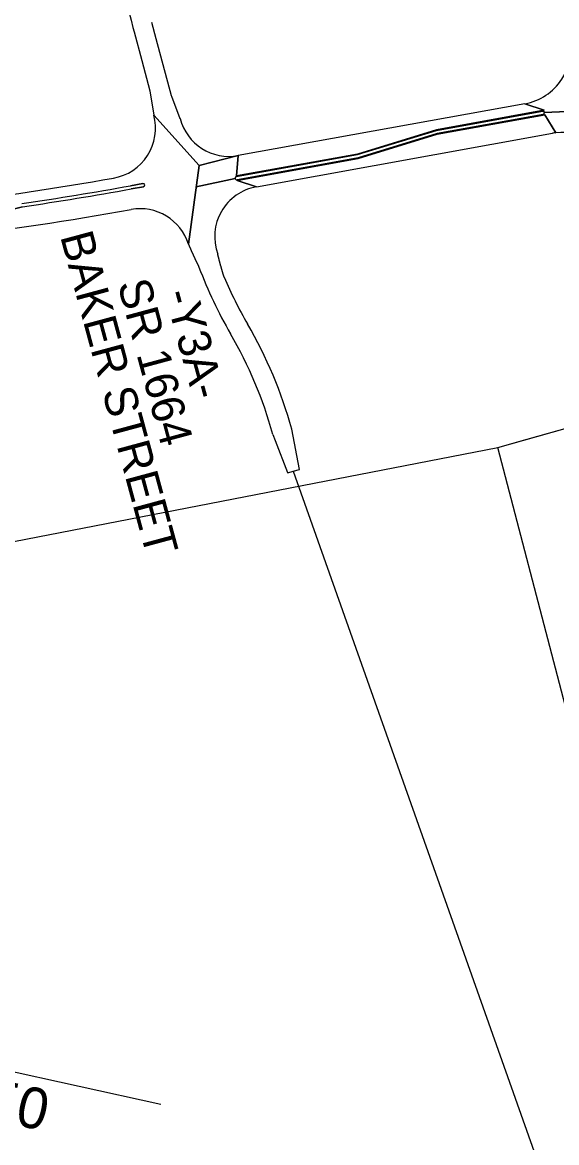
# Model space of a CAD drawing. Extents: x 1609449 to 1623942, y 894240 to 902860.
# Drawn here: x 1620757 to 1621409, y 896944 to 898313 of the extents above; entities that cross this region are included whole.
import ezdxf

# ---------------------------------------------------------------- set-up
doc = ezdxf.new("R2010")
doc.units = 0
for name, color, linetype in [('Old_Level_1', 7, 'Continuous'), ('Prop Horizontal Alignment Station Label', 7, 'Continuous'), ('Prop Roadway Bridge', 7, 'Continuous'), ('Prop Shade Light', 7, 'Continuous'), ('Prop Shade Medium', 7, 'Continuous')]:
    doc.layers.add(name, color=color, linetype=linetype)

msp = doc.modelspace()

# ---------------------------------------------------------------- linework, layer by layer
at = {"layer": 'Old_Level_1'}
for points in [[(1620396.2, 898448.3), (1620661.8, 898448.3), (1620661.8, 897662.4), (1621336.9, 897793.5), (1621466.5, 897830.2), (1621864, 897934.4), (1622007.2, 897969.4), (1621831.8, 898938.5), (1620355.8, 898671.4)], [(1621336.9, 897793.5), (1621372.5, 897803.4), (1621466.5, 897830.2), (1621756.4, 897907.9), (1621864, 897934.4), (1622015.4, 897355), (1621487.4, 897217.1)]]:
    msp.add_lwpolyline(points, close=True, dxfattribs=at)
at = {"layer": 'Prop Horizontal Alignment Station Label'}
msp.add_line((1621087, 897764.3), (1621535, 896499.9), dxfattribs=at)
at = {"layer": 'Prop Roadway Bridge'}
msp.add_line((1620274, 897134.9), (1620925.3, 896991.4), dxfattribs=at)
at = {"layer": 'Prop Shade Light'}
for p, q in [((1620912, 898229), (1620916.8, 898199.3)), ((1621370, 898213.2), (1621019.9, 898149.8)), ((1621393.4, 898205.2), (1621370, 898213.2)), ((1621393.4, 898205.2), (1621370, 898213.2)), ((1621370, 898213.2), (1621393.4, 898205.2)), ((1620916.8, 898199.3), (1620972.2, 898137.9)), ((1620972.2, 898137.9), (1620916.8, 898199.3)), ((1620916.8, 898199.3), (1620972.2, 898137.9)), ((1621261.8, 898181.4), (1621393.4, 898205.2)), ((1621393.4, 898205.2), (1621261.8, 898181.4)), ((1621262, 898180.7), (1621391.6, 898204.1)), ((1621392.3, 898200.2), (1621262.7, 898176.8)), ((1621394.4, 898199.8), (1621262.8, 898176)), ((1621262.8, 898176), (1621394.4, 898199.8)), ((1621393.9, 898202.3), (1621497.1, 898207.8)), ((1621497.1, 898207.8), (1621393.9, 898202.3)), ((1621393.9, 898202.3), (1621497.1, 898207.8)), ((1621408, 898177.1), (1621394.4, 898199.8)), ((1621407.6, 898177.7), (1621394.4, 898199.8)), ((1621394.4, 898199.8), (1621407.6, 898177.7)), ((1621042.2, 898111.7), (1621403.4, 898177.1)), ((1621165.4, 898151.8), (1621261.8, 898181.4)), ((1621261.8, 898181.4), (1621165.4, 898151.8)), ((1621165.5, 898151), (1621262, 898180.7)), ((1621262.7, 898176.8), (1621166.2, 898147.1)), ((1621262.8, 898176), (1621166.3, 898146.4)), ((1621166.3, 898146.4), (1621262.8, 898176)), ((1620972.2, 898137.9), (1621019.9, 898149.8)), ((1620972.2, 898137.9), (1621019.9, 898149.8)), ((1621019.9, 898149.8), (1620972.2, 898137.9)), ((1621017.8, 898125.1), (1621165.4, 898151.8)), ((1621165.4, 898151.8), (1621017.8, 898125.1)), ((1621017.8, 898125.1), (1621019.9, 898149.8)), ((1621019.9, 898149.8), (1621017.8, 898125.1)), ((1621017.8, 898125.1), (1621019.9, 898149.8)), ((1621017.9, 898124.3), (1621165.5, 898151)), ((1621166.2, 898147.1), (1621018.6, 898120.4)), ((1621166.3, 898146.4), (1621018.7, 898119.6)), ((1621018.7, 898119.6), (1621166.3, 898146.4)), ((1620972.2, 898137.9), (1620959.2, 898041.5)), ((1620959.2, 898041.5), (1620972.2, 898137.9)), ((1620972.2, 898137.9), (1620968.7, 898111.9)), ((1620888.4, 898113.1), (1620903.7, 898115.8)), ((1621016.3, 898122), (1620968.7, 898111.9)), ((1621016.3, 898122), (1620968.7, 898111.9)), ((1620968.7, 898111.9), (1621016.3, 898122)), ((1621018.7, 898119.6), (1621042.2, 898111.7)), ((1621018.7, 898119.6), (1621042.2, 898111.7)), ((1621042.2, 898111.7), (1621018.7, 898119.6)), ((1620904.4, 898111.9), (1620889.1, 898109.1)), ((1620968.7, 898111.9), (1620959.2, 898041.5)), ((1621094.9, 897766.4), (1621085.3, 897815.6))]:
    msp.add_line(p, q, dxfattribs=at)
for points in [[(1620891.5, 898306.4), (1620892.9, 898300.9), (1620902.1, 898266.1), (1620912, 898229)], [(1620938.5, 898222.9), (1620919.9, 898292.6), (1620914.7, 898312.5)], [(1620949, 898194.9), (1620938.8, 898221.9), (1620938.5, 898222.9)], [(1621062.2, 897809.3), (1621065, 897802.1), (1621065, 897802.1), (1621080.3, 897762.7), (1621080.4, 897762.4)], [(1621080.4, 897762.4), (1621087, 897764.3), (1621094.9, 897766.4)]]:
    msp.add_lwpolyline(points, dxfattribs=at)
for centre, radius, start, end in [((1621418.2, 898446.2), 545, 179.3265, 194.8727), ((1621357.9, 898280.1), 68, 280.2581, 13.8394), ((1620856.9, 898183.4), 62, 279.9888, 14.8727), ((1621391.9, 898202.2), 2, 4.5811, 100.2599), ((1621391.9, 898202.2), 2, 280.2599, 284.1231), ((1621391.9, 898202.2), 2, 284.1231, 4.5811), ((1621008.9, 898210.9), 62, 194.8727, 280.2581), ((1621415.6, 898110.2), 68, 96.6994, 100.2599), ((1621415.6, 898110.2), 68, 14.985, 96.6994), ((1620177.4, 902041.2), 3979.2, 276.992, 279.9888), ((1620904, 898113.9), 2, 280.2599, 100.2599), ((1621018.3, 898122.3), 2, 100.2599, 188.9181), ((1621018.3, 898122.3), 2, 188.9181, 280.2599), ((1620177.4, 902041.2), 3992, 278.333, 280.2599), ((1620177.4, 902041.2), 3996, 278.333, 280.2599), ((1621053.2, 898050.7), 62, 100.2599, 199.8507), ((1620177.4, 902041.2), 4020.7, 276.9195, 280.1956), ((1620900.1, 898023), 62, 17.4099, 100.1956), ((1621482.1, 898205.5), 545, 200.6397, 210.1014), ((1621482.1, 898205.5), 521, 203.0756, 210.1014), ((1620559.9, 897670.9), 545, 15.403, 30.1014), ((1620559.9, 897670.9), 521, 15.403, 30.1014)]:
    msp.add_arc(centre, radius, start, end, dxfattribs=at)
for points in [[(1620959.2, 898041.5), (1620959.4, 898041.1), (1620959.6, 898040.7), (1620959.7, 898040.4), (1620959.9, 898040), (1620960.1, 898039.6), (1620960.2, 898039.2), (1620960.4, 898038.8), (1620960.6, 898038.4), (1620960.7, 898038), (1620960.9, 898037.7), (1620961.1, 898037.3), (1620961.2, 898036.9), (1620961.4, 898036.5), (1620961.6, 898036.1), (1620961.7, 898035.7), (1620961.9, 898035.4), (1620962.1, 898035), (1620962.2, 898034.6), (1620962.4, 898034.2), (1620962.6, 898033.8), (1620962.7, 898033.4), (1620962.9, 898033.1), (1620963.1, 898032.7), (1620963.3, 898032.3), (1620963.4, 898032.1)], [(1620963.4, 898032.1), (1620963.4, 898031.9), (1620963.6, 898031.5), (1620963.8, 898031.2), (1620963.9, 898030.8), (1620964.1, 898030.4), (1620964.3, 898030), (1620964.5, 898029.6), (1620964.6, 898029.3), (1620964.8, 898028.9), (1620965, 898028.5), (1620965.1, 898028.1), (1620965.3, 898027.7), (1620965.5, 898027.4), (1620965.7, 898027), (1620965.8, 898026.6), (1620966, 898026.2), (1620966.2, 898025.8), (1620966.4, 898025.5), (1620966.5, 898025.1), (1620966.7, 898024.7), (1620966.9, 898024.3), (1620967.1, 898023.9), (1620967.2, 898023.6), (1620967.4, 898023.2), (1620967.6, 898022.8), (1620967.6, 898022.7)], [(1620967.6, 898022.7), (1620967.8, 898022.4), (1620967.9, 898022.1), (1620968.1, 898021.7), (1620968.3, 898021.3), (1620968.5, 898020.9), (1620968.7, 898020.5), (1620968.8, 898020.2), (1620969, 898019.8), (1620969.2, 898019.4), (1620969.4, 898019), (1620969.6, 898018.7), (1620969.7, 898018.3), (1620969.9, 898017.9), (1620970.1, 898017.5), (1620970.3, 898017.2), (1620970.5, 898016.8), (1620970.6, 898016.4), (1620970.8, 898016), (1620971, 898015.7), (1620971.2, 898015.3), (1620971.4, 898014.9), (1620971.6, 898014.5), (1620971.7, 898014.2), (1620972.1, 898013.4)], [(1620997.4, 898020.1), (1620997.3, 898020.4), (1620997.2, 898020.8), (1620997.1, 898021.2), (1620997, 898021.6), (1620996.9, 898021.9), (1620996.8, 898022.3), (1620996.7, 898022.7), (1620996.6, 898023.1), (1620996.5, 898023.5), (1620996.4, 898023.9), (1620996.3, 898024.2), (1620996.2, 898024.6), (1620996.1, 898025), (1620996, 898025.4), (1620995.9, 898025.8), (1620995.8, 898026.2), (1620995.7, 898026.6), (1620995.6, 898026.9), (1620995.5, 898027.3), (1620995.4, 898027.7), (1620995.3, 898028.1), (1620995.2, 898028.5), (1620995.1, 898028.9), (1620995, 898029.2), (1620994.9, 898029.6)], [(1621000, 898010.7), (1621000, 898010.8), (1620999.8, 898011.2), (1620999.7, 898011.6), (1620999.6, 898012), (1620999.5, 898012.4), (1620999.4, 898012.8), (1620999.3, 898013.1), (1620999.2, 898013.5), (1620999.1, 898013.9), (1620999, 898014.3), (1620998.9, 898014.7), (1620998.8, 898015.1), (1620998.7, 898015.4), (1620998.5, 898015.8), (1620998.4, 898016.2), (1620998.3, 898016.6), (1620998.2, 898017), (1620998.1, 898017.3), (1620998, 898017.7), (1620997.9, 898018.1), (1620997.8, 898018.5), (1620997.7, 898018.9), (1620997.6, 898019.3), (1620997.5, 898019.6), (1620997.4, 898020), (1620997.4, 898020.1)]]:
    msp.add_spline(points, degree=3, dxfattribs=at)
msp.add_open_spline([(1621002.8, 898001.3), (1621002.7, 898001.6), (1621002.7, 898001.8), (1621002.6, 898002.1), (1621002.5, 898002.2), (1621002.5, 898002.3), (1621002.5, 898002.5), (1621002.4, 898002.6), (1621002.4, 898002.7), (1621002.3, 898002.8), (1621002.3, 898003), (1621002.3, 898003.1), (1621002.2, 898003.2), (1621002.2, 898003.3), (1621002.2, 898003.5), (1621002.1, 898003.6), (1621002.1, 898003.7), (1621002, 898003.9), (1621002, 898004), (1621002, 898004.1), (1621001.9, 898004.2), (1621001.9, 898004.4), (1621001.8, 898004.5), (1621001.8, 898004.6), (1621001.8, 898004.7), (1621001.7, 898004.9), (1621001.7, 898005), (1621001.7, 898005.1), (1621001.6, 898005.3), (1621001.6, 898005.4), (1621001.5, 898005.5), (1621001.5, 898005.6), (1621001.5, 898005.8), (1621001.4, 898005.9), (1621001.4, 898006), (1621001.3, 898006.1), (1621001.3, 898006.3), (1621001.3, 898006.4), (1621001.2, 898006.5), (1621001.2, 898006.7), (1621001.2, 898006.8), (1621001.1, 898006.9), (1621001.1, 898007), (1621001, 898007.2), (1621001, 898007.3), (1621001, 898007.4), (1621000.9, 898007.5), (1621000.9, 898007.7), (1621000.9, 898007.8), (1621000.8, 898007.9), (1621000.8, 898008), (1621000.7, 898008.2), (1621000.7, 898008.3), (1621000.7, 898008.4), (1621000.6, 898008.6), (1621000.6, 898008.7), (1621000.6, 898008.8), (1621000.5, 898008.9), (1621000.5, 898009.1), (1621000.4, 898009.2), (1621000.4, 898009.3), (1621000.4, 898009.4), (1621000.3, 898009.6), (1621000.3, 898009.7), (1621000.3, 898009.8), (1621000.2, 898010), (1621000.2, 898010.1), (1621000.1, 898010.2), (1621000.1, 898010.3), (1621000.1, 898010.5), (1621000, 898010.5), (1621000, 898010.6), (1621000, 898010.7)], degree=3, dxfattribs=at)
at = {"layer": 'Prop Shade Medium'}
for p, q in [((1621391.6, 898204.1), (1621262, 898180.7)), ((1621262.7, 898176.8), (1621392.3, 898200.2)), ((1621262, 898180.7), (1621165.5, 898151)), ((1621166.2, 898147.1), (1621262.7, 898176.8)), ((1621165.5, 898151), (1621017.9, 898124.3)), ((1621018.6, 898120.4), (1621166.2, 898147.1)), ((1620903.7, 898115.8), (1620888.4, 898113.1)), ((1620889.1, 898109.1), (1620904.4, 898111.9))]:
    msp.add_line(p, q, dxfattribs=at)
for centre, radius, start, end in [((1621391.9, 898202.2), 2, 280.2599, 100.2599), ((1620904, 898113.9), 2, 280.2599, 100.2599), ((1621018.3, 898122.3), 2, 100.2599, 280.2599), ((1620177.4, 902041.2), 3992, 278.333, 280.2599), ((1620177.4, 902041.2), 3996, 278.333, 280.2599)]:
    msp.add_arc(centre, radius, start, end, dxfattribs=at)
msp.add_spline([(1620736, 898082.2), (1620736.1, 898082.2), (1620736.8, 898082.4), (1620737.4, 898082.6), (1620738.1, 898082.7), (1620738.8, 898082.9), (1620739.4, 898083.1), (1620740.1, 898083.2), (1620740.7, 898083.4), (1620741.4, 898083.6), (1620742.1, 898083.7), (1620742.7, 898083.9), (1620743.4, 898084.1), (1620744, 898084.2), (1620744.7, 898084.4), (1620745.3, 898084.6), (1620746, 898084.7), (1620746.7, 898084.9), (1620747.3, 898085.1), (1620748, 898085.2), (1620748.6, 898085.4), (1620749.3, 898085.6), (1620750, 898085.7), (1620750.6, 898085.9), (1620751.3, 898086.1), (1620751.9, 898086.2), (1620752.6, 898086.4), (1620753.2, 898086.6), (1620753.9, 898086.8), (1620754.6, 898086.9), (1620755.2, 898087.1), (1620756.5, 898087.4)], degree=3, dxfattribs=at)

# ---------------------------------------------------------------- texts
at = {"layer": 'Prop Horizontal Alignment Station Label'}
for s, p in [('BAKER STREET', (1620802.4, 898051.4)), ('SR 1664', (1620872.4, 897993.3)), ('-Y3A-', (1620929.9, 897981.6))]:
    msp.add_text(s, height=40, rotation=285.1215, dxfattribs=at).set_placement(p)
at = {"layer": 'Prop Roadway Bridge'}
msp.add_text('-L- STA 33+76.50', height=50, rotation=347.5755, dxfattribs=at).set_placement((1620265.1, 897072.4))

doc.saveas('drawing.dxf')
